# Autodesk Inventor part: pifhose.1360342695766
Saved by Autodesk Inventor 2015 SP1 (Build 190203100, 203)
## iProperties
IsCustomPart: 1
Company: Parker Hannifin
Created: 2013-02
Material: Rubber
Description: Tömlő
Document SubType Name: Modeling
Standard: Parker
Designer: Marci
Manufacturer: Parker
Language: hu-HU
Size Designation: 1/4 - 5
Categories: <MemberInstance><Categories><Category DisplayName="Csővezetékek" InternalName="4347fa0f-2144-441d-94cd-e3e15c92b736" Mnemonic="TUBEANDPIPE"><CategoryParameter D
Stock Number: Parker hidraulikatömlő - No Skive 1/4
Density: 1 g/cm^3
Appearance: Rubber - Black - Version 1.1
NAME: PIPING: Parker Hydraulic Hose - No Skive
DATA: <meta><inlinegroups number="1" deflen="12.7"></inlinegroups><connections number="2"></connections><angles><a>3.14159265358979</a></angles></meta>
L: 7,377 in
PL: 7,377 in
RPL: 7,500 in
OPL: 7,377 in
ROPL: 7,500 in
Author: Marci
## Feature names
1. Sweep1
## Parameters: ID = 6.35 mm, OD = 14.986 mm, L = 187.3758 mm, PL = 187.3758 mm, Size_Designation = 2.5 mm, d6 = 0, RPL = 190.5 mm, OPL = 187.3758 mm, ROPL = 190.5 mm, d7 = 0
